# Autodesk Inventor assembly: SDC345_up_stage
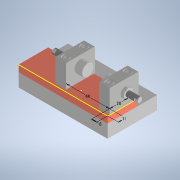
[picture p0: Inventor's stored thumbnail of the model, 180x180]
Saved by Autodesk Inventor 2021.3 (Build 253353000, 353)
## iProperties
Created: 2022-02
Part Number: SDC345_up_stage
Document SubType Name: Assembly
Designer: kengo
Author: kengo
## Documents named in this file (7)
- C:\Users\kengo\Documents\S2S_frame\SDC345\frame_misumi_ver12\upper-stage\SDC345_up_stage.iam
- C:\Users\kengo\Documents\S2S_frame\SDC345\frame_misumi_ver12\upper-stage\SDC_upper_stage_AlPlate.ipt
- C:\Users\kengo\Documents\S2S_frame\SDC345\frame_misumi_ver12\upper-stage\SDC_upper_stage_CFPlate.ipt
- C:\Users\kengo\Documents\S2S_frame\SDC345\frame_misumi_ver12\upper-stage\CBM12-25.ipt
- C:\Users\kengo\Documents\S2S_frame\SDC345\frame_misumi_ver12\upper-stage\AJSN8-20.ipt
- C:\Users\kengo\Documents\S2S_frame\SDC345\frame_misumi_ver12\upper-stage\SCB6-55.ipt
- C:\Users\kengo\Documents\S2S_frame\SDC345\frame_misumi_ver12\upper-stage\UNST8-40.iam
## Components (13 placed, 6 different names)
1. SDC_upper_stage_AlPlate:1 — 回転:1, 回転:2, メイト:1, フラッシュ:1, フラッシュ:2, 回転:9
2. SDC_upper_stage_CFPlate:1 — メイト:1, フラッシュ:1, フラッシュ:2, 挿入:1, 挿入:2, 挿入:3, 挿入:4
3. CBM12-25:1 — 回転:1
4. CBM12-25:2 — 回転:2
5. AJSN8-20:1 — 挿入:1, 挿入:4, 回転:3, 回転:4, 回転:7
6. AJSN8-20:2 — 挿入:2, 挿入:3, 回転:5, 回転:6, 回転:8
7. SCB6-55:1 — 回転:3
8. SCB6-55:2 — 回転:4
9. SCB6-55:3 — 回転:5
10. SCB6-55:4 — 回転:6
11. UNST8-40:1 [sub-assembly] — 回転:7
12. UNST8-40:2 [sub-assembly] — 回転:8
13. UNST8-40:3 [sub-assembly] — 回転:9
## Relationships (16: RevoluteJoint 9, Insert 4, Flush 2, Mate 1)
- 回転:1 [RevoluteJoint]: SDC_upper_stage_AlPlate:1 ↔ CBM12-25:1
- 回転:2 [RevoluteJoint]: SDC_upper_stage_AlPlate:1 ↔ CBM12-25:2
- メイト:1 [Mate]: SDC_upper_stage_AlPlate:1 ↔ SDC_upper_stage_CFPlate:1
- フラッシュ:1 [Flush]: SDC_upper_stage_AlPlate:1 ↔ SDC_upper_stage_CFPlate:1
- フラッシュ:2 [Flush]: SDC_upper_stage_AlPlate:1 ↔ SDC_upper_stage_CFPlate:1
- 挿入:1 [Insert]: SDC_upper_stage_CFPlate:1 ↔ AJSN8-20:1
- 挿入:2 [Insert]: SDC_upper_stage_CFPlate:1 ↔ AJSN8-20:2
- 挿入:3 [Insert]: SDC_upper_stage_CFPlate:1 ↔ AJSN8-20:2
- 挿入:4 [Insert]: SDC_upper_stage_CFPlate:1 ↔ AJSN8-20:1
- 回転:3 [RevoluteJoint]: AJSN8-20:1 ↔ SCB6-55:1
- 回転:4 [RevoluteJoint]: AJSN8-20:1 ↔ SCB6-55:2
- 回転:5 [RevoluteJoint]: AJSN8-20:2 ↔ SCB6-55:3
- 回転:6 [RevoluteJoint]: AJSN8-20:2 ↔ SCB6-55:4
- 回転:7 [RevoluteJoint]: AJSN8-20:1 ↔ UNST8-40:1
- 回転:8 [RevoluteJoint]: AJSN8-20:2 ↔ UNST8-40:2
- 回転:9 [RevoluteJoint]: SDC_upper_stage_AlPlate:1 ↔ UNST8-40:3
